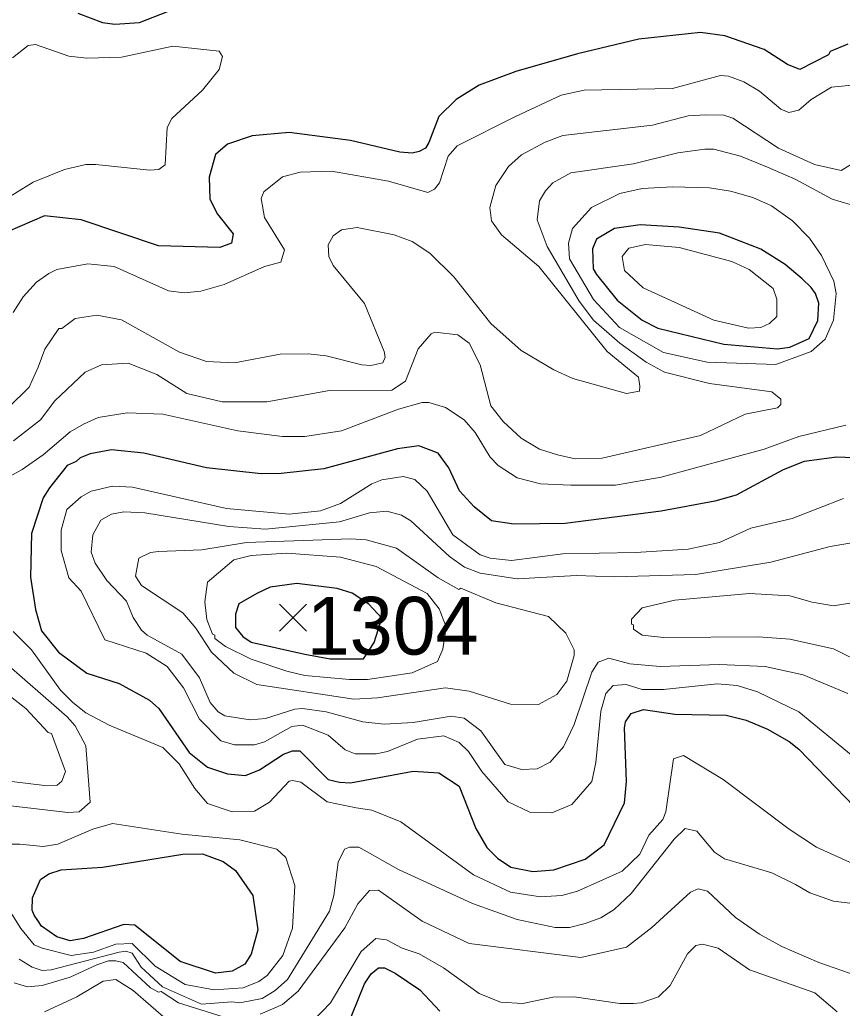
# Model space of a CAD drawing. Extents: x 423 to 448.8, y 7456.3 to 7484.
# Drawn here: x 432.388 to 433.527, y 7475.791 to 7477.16 of the extents above; entities that cross this region are included whole.
import ezdxf
from ezdxf.enums import TextEntityAlignment as Align

# ---------------------------------------------------------------- set-up
doc = ezdxf.new("R2010")
doc.units = 0
doc.header["$LTSCALE"] = 0.032
for name, color, linetype, lineweight in [('1', 7, 'Continuous', 25), ('2', 7, 'Continuous', 13), ('21', 7, 'Continuous', 25)]:
    doc.layers.add(name, color=color, linetype=linetype, lineweight=lineweight)
doc.layers.add('61', color=7, linetype='Continuous')

msp = doc.modelspace()

# ---------------------------------------------------------------- linework, layer by layer
at = {"layer": '1'}
for points in [[(432.4688, 7477.1694), (432.5028, 7477.1562), (432.5198, 7477.1539), (432.5538, 7477.1562), (432.6343, 7477.1879)], [(433.5346, 7477.1261), (433.5098, 7477.116), (433.5075, 7477.1114), (433.4681, 7477.0912), (433.451, 7477.0982), (433.4186, 7477.1191), (433.3644, 7477.1377), (433.3304, 7477.1423), (433.2453, 7477.133), (433.1602, 7477.1129), (433.0751, 7477.0882), (433.0241, 7477.0696), (432.9924, 7477.0495), (432.9684, 7477.0263), (432.9545, 7476.9899), (432.9498, 7476.9822), (432.9413, 7476.9775), (432.9313, 7476.9752), (432.9143, 7476.9768), (432.8462, 7476.993), (432.7611, 7477.0039), (432.7101, 7476.9992), (432.676, 7476.9876), (432.659, 7476.9737), (432.6505, 7476.942), (432.6512, 7476.9118), (432.6621, 7476.8909), (432.6837, 7476.8638), (432.6814, 7476.8507), (432.6652, 7476.8445), (432.5801, 7476.8468), (432.4734, 7476.8832), (432.4223, 7476.8886), (432.3713, 7476.8662)], [(433.5771, 7476.5522), (433.5191, 7476.5544), (433.4742, 7476.5483), (433.4449, 7476.5367), (433.3799, 7476.5019), (433.3505, 7476.4934), (433.2762, 7476.4794), (433.1432, 7476.4624), (433.072, 7476.4616), (433.0411, 7476.4663), (433.0171, 7476.4856), (432.997, 7476.508), (432.9823, 7476.5398), (432.9676, 7476.5599), (432.9406, 7476.5699), (432.9112, 7476.5661), (432.8091, 7476.5382), (432.7503, 7476.532), (432.7224, 7476.5313), (432.6466, 7476.5398)], [(432.6466, 7476.5398), (432.56, 7476.5599), (432.5152, 7476.5645), (432.4858, 7476.5591), (432.4718, 7476.5537), (432.4664, 7476.5483), (432.454, 7476.5429), (432.4293, 7476.5119), (432.4208, 7476.498), (432.4045, 7476.4485), (432.403, 7476.3882), (432.41, 7476.3433), (432.4184, 7476.3139), (432.4417, 7476.2845), (432.4811, 7476.2551), (432.526, 7476.2412), (432.5677, 7476.218), (432.5809, 7476.2064), (432.6227, 7476.1453), (432.6482, 7476.1252), (432.676, 7476.1159), (432.7007, 7476.1136), (432.7201, 7476.1213), (432.7534, 7476.143), (432.7658, 7476.1476), (432.7758, 7476.1476), (432.8152, 7476.1082), (432.8307, 7476.1043), (432.8462, 7476.1035), (432.9328, 7476.1198), (432.9684, 7476.1174), (432.9963, 7476.0989), (433.0194, 7476.0401), (433.0349, 7476.0138), (433.0496, 7475.9991), (433.0681, 7475.9868), (433.0983, 7475.9806), (433.1277, 7475.9829), (433.1711, 7475.9976), (433.1973, 7476.0177), (433.2252, 7476.0757), (433.2283, 7476.1051), (433.2252, 7476.1794), (433.2267, 7476.1878), (433.2345, 7476.1994), (433.2515, 7476.2048), (433.2948, 7476.1987), (433.366, 7476.1971), (433.3938, 7476.1902), (433.4232, 7476.1778), (433.4533, 7476.1608), (433.4665, 7476.1499), (433.5562, 7476.0571)], [(432.8392, 7475.7601), (432.8655, 7475.8251), (432.8748, 7475.839), (432.8848, 7475.8475), (432.8933, 7475.8475), (432.9081, 7475.8398), (432.9421, 7475.8166), (432.9699, 7475.7872)]]:
    msp.add_lwpolyline(points, dxfattribs=at)
for points in [[(433.4837, 7476.7893), (433.4711, 7476.8012), (433.4479, 7476.8213), (433.4139, 7476.8422), (433.3567, 7476.8646), (433.301, 7476.8731), (433.2469, 7476.8762), (433.2113, 7476.8708), (433.1865, 7476.8561), (433.1811, 7476.843), (433.1818, 7476.8151), (433.1865, 7476.8074), (433.2151, 7476.7718), (433.2499, 7476.7439), (433.2716, 7476.7331), (433.3629, 7476.7107), (433.4371, 7476.7045), (433.4541, 7476.7068), (433.4808, 7476.7188), (433.4928, 7476.7436), (433.4943, 7476.7676), (433.4897, 7476.7811)], [(432.7828, 7476.2814), (432.8181, 7476.2753), (432.8639, 7476.2753), (432.879, 7476.2979), (432.8893, 7476.3315), (432.8715, 7476.3507), (432.8486, 7476.3661), (432.8276, 7476.3727), (432.7719, 7476.3796), (432.7348, 7476.3743), (432.7163, 7476.3657), (432.6915, 7476.3511), (432.6869, 7476.3371), (432.6869, 7476.3186), (432.6969, 7476.3062), (432.7085, 7476.2984)], [(432.4455, 7475.9828), (432.5028, 7475.9868), (432.6142, 7476.0045), (432.6412, 7476.0053), (432.6699, 7475.9945), (432.6868, 7475.9821), (432.7108, 7475.9473), (432.7178, 7475.9001), (432.7085, 7475.8661), (432.7, 7475.8522), (432.6822, 7475.8429), (432.659, 7475.8398), (432.6103, 7475.856), (432.5476, 7475.9063), (432.5322, 7475.9071), (432.4765, 7475.8877), (432.4579, 7475.8846), (432.4394, 7475.8901), (432.4184, 7475.9048), (432.4133, 7475.9127), (432.4084, 7475.9202), (432.4053, 7475.9272), (432.4061, 7475.9442), (432.4169, 7475.9697), (432.4285, 7475.9775)]]:
    msp.add_lwpolyline(points, close=True, dxfattribs=at)
at = {"layer": '2'}
for points in [[(432.3782, 7477.1075), (432.3999, 7477.1245), (432.41, 7477.126), (432.4564, 7477.1098), (432.4811, 7477.1067), (432.5291, 7477.1082), (432.6002, 7477.1237), (432.6644, 7477.1167), (432.6691, 7477.109), (432.6644, 7477.0912), (432.6412, 7477.0626), (432.5986, 7477.0232), (432.5925, 7477.0108), (432.5894, 7476.959), (432.5809, 7476.9528), (432.5678, 7476.952), (432.4935, 7476.9598), (432.4796, 7476.9598), (432.4502, 7476.9528), (432.4069, 7476.935), (432.3048, 7476.8723)], [(432.379, 7476.7548), (432.3929, 7476.7765), (432.4115, 7476.7965), (432.4285, 7476.8089), (432.4394, 7476.8143), (432.4827, 7476.8221), (432.519, 7476.8182), (432.5941, 7476.7849), (432.6157, 7476.7819), (432.6389, 7476.7842), (432.6714, 7476.7935), (432.7271, 7476.8182), (432.7495, 7476.8244), (432.7549, 7476.8414), (432.727, 7476.8863), (432.7224, 7476.9126), (432.7263, 7476.9218), (432.7518, 7476.9427), (432.7766, 7476.9489), (432.8199, 7476.9505), (432.8988, 7476.9366), (432.9529, 7476.9211), (432.9622, 7476.9257), (432.9692, 7476.9342), (432.9815, 7476.9714), (432.9939, 7476.9853), (433.0743, 7477.0263), (433.1378, 7477.0557), (433.1695, 7477.0626), (433.2917, 7477.0649), (433.3582, 7477.0828), (433.3691, 7477.082), (433.3907, 7477.0742), (433.4124, 7477.0611), (433.4418, 7477.0363), (433.4526, 7477.0317), (433.4665, 7477.0348), (433.4835, 7477.0495), (433.5121, 7477.0665), (433.5547, 7477.0711)], [(433.3134, 7477.0271), (433.2639, 7477.0139), (433.1401, 7477), (433.1154, 7476.9907), (433.0829, 7476.9729), (433.065, 7476.9567), (433.0473, 7476.9304), (433.0388, 7476.9002), (433.0411, 7476.8817), (433.055, 7476.8623), (433.1068, 7476.8182), (433.2012, 7476.7006), (433.2445, 7476.6651), (433.2468, 7476.6527), (433.2461, 7476.6457), (433.2283, 7476.6426), (433.154, 7476.6635), (433.1277, 7476.6751), (433.0821, 7476.7022), (433.0403, 7476.7393), (432.9893, 7476.8043), (432.956, 7476.8368), (432.9313, 7476.853), (432.9065, 7476.8623), (432.8555, 7476.8723), (432.8338, 7476.8692), (432.8222, 7476.8608), (432.8153, 7476.8484), (432.816, 7476.8322), (432.8222, 7476.8198), (432.8655, 7476.7672), (432.8926, 7476.7007), (432.8941, 7476.6929), (432.891, 7476.6852), (432.874, 7476.6813), (432.8617, 7476.6821), (432.8122, 7476.6945), (432.7874, 7476.6976), (432.7487, 7476.6968), (432.6853, 7476.6852), (432.6466, 7476.6867), (432.6095, 7476.6999), (432.529, 7476.7447), (432.495, 7476.7509), (432.4649, 7476.7463), (432.4463, 7476.7324), (432.4424, 7476.7324), (432.4231, 7476.7038), (432.4138, 7476.679), (432.4014, 7476.6512), (432.3728, 7476.6233)], [(433.5384, 7476.959), (433.5253, 7476.9512), (433.4882, 7476.9597), (433.4387, 7476.9822), (433.3752, 7477.024), (433.3629, 7477.0278), (433.3381, 7477.0286), (433.3134, 7477.0271)], [(433.5377, 7476.9041), (433.5129, 7476.9118), (433.4626, 7476.9389), (433.4232, 7476.9559), (433.3861, 7476.9714), (433.3489, 7476.9807), (433.3366, 7476.9807), (433.2994, 7476.976), (433.2376, 7476.9605), (433.1509, 7476.9482), (433.1262, 7476.9342), (433.1161, 7476.9234), (433.1076, 7476.9095), (433.1045, 7476.8832), (433.1184, 7476.8461), (433.1625, 7476.7703), (433.1826, 7476.744), (433.219, 7476.7123), (433.2553, 7476.686), (433.2809, 7476.672), (433.3428, 7476.6565), (433.4294, 7476.6449)], [(433.4294, 7476.6449), (433.4418, 7476.6349), (433.4418, 7476.6272), (433.4371, 7476.6225), (433.3923, 7476.614), (433.3304, 7476.5846), (433.1943, 7476.5529), (433.1571, 7476.5522), (433.1324, 7476.5575), (433.1076, 7476.5653), (433.0821, 7476.5807), (433.0573, 7476.604), (433.0403, 7476.6256), (433.0256, 7476.6821), (433.0102, 7476.7122), (432.9947, 7476.7239), (432.963, 7476.7277), (432.9576, 7476.7254), (432.9398, 7476.7045), (432.922, 7476.6596), (432.9034, 7476.6473), (432.8168, 7476.6465), (432.7302, 7476.6311), (432.6683, 7476.6311), (432.6195, 7476.6426), (432.5778, 7476.6689), (432.5384, 7476.6844), (432.5012, 7476.6821), (432.4788, 7476.672), (432.437, 7476.6326), (432.4169, 7476.6063), (432.3798, 7476.5769)], [(433.5315, 7476.5985), (433.4665, 7476.5831), (433.4186, 7476.5653), (433.2762, 7476.5266), (433.2128, 7476.5158), (433.1509, 7476.5158), (433.1092, 7476.5173), (433.0767, 7476.5258), (433.0504, 7476.5428), (433.0395, 7476.5545), (433.0187, 7476.5885), (433.0032, 7476.6063), (432.9776, 7476.6233), (432.9545, 7476.6303), (432.9452, 7476.6303), (432.9127, 7476.621), (432.8338, 7476.5908), (432.7828, 7476.5831), (432.7518, 7476.5831), (432.69, 7476.5908), (432.5863, 7476.614), (432.5368, 7476.6156), (432.4966, 7476.6094), (432.4764, 7476.6001), (432.4579, 7476.5893), (432.4208, 7476.5575), (432.3914, 7476.5375), (432.3372, 7476.5073)], [(433.5284, 7476.4972), (433.4572, 7476.4694), (433.4, 7476.4562), (433.3567, 7476.4361), (433.3134, 7476.4269), (433.2407, 7476.4222), (433.1401, 7476.4207), (433.069, 7476.4114), (433.0396, 7476.4145), (433.0256, 7476.4191), (432.9877, 7476.4469), (432.9521, 7476.5073), (432.9351, 7476.5235), (432.9189, 7476.5274), (432.8895, 7476.5228), (432.8756, 7476.5173), (432.8323, 7476.4902), (432.8044, 7476.4802), (432.7611, 7476.4756), (432.6745, 7476.4833), (432.5445, 7476.5127), (432.5167, 7476.5142), (432.4873, 7476.5073), (432.4734, 7476.4995), (432.4533, 7476.4818), (432.4455, 7476.4532), (432.4455, 7476.4253), (432.4564, 7476.3874), (432.4734, 7476.3688), (432.5059, 7476.3015), (432.5631, 7476.283), (432.5925, 7476.2644), (432.6149, 7476.235), (432.6373, 7476.1917), (432.6668, 7476.1615), (432.6853, 7476.1561), (432.7132, 7476.1561), (432.7271, 7476.16), (432.765, 7476.1816), (432.7797, 7476.1832), (432.8152, 7476.1693), (432.8385, 7476.1492), (432.8524, 7476.1437), (432.8818, 7476.1437), (432.8972, 7476.1468), (432.939, 7476.1639), (432.9754, 7476.1685), (432.9963, 7476.1592), (433.0094, 7476.1468), (433.0279, 7476.119), (433.0643, 7476.0773), (433.0953, 7476.0625), (433.1246, 7476.0618), (433.1524, 7476.0734), (433.1803, 7476.1051), (433.1857, 7476.1314), (433.1927, 7476.2026), (433.1996, 7476.2273), (433.2097, 7476.2381), (433.2275, 7476.2397), (433.2499, 7476.2327), (433.2793, 7476.2327), (433.3536, 7476.2404), (433.3814, 7476.2381), (433.4093, 7476.2296), (433.4665, 7476.2018), (433.5547, 7476.1291)], [(433.5887, 7476.4439), (433.5098, 7476.4307), (433.4278, 7476.409), (433.3242, 7476.392), (433.2113, 7476.3889), (433.1587, 7476.3905), (433.0767, 7476.3858), (433.0256, 7476.3936), (433.004, 7476.4021), (432.9831, 7476.4168), (432.9297, 7476.4663), (432.9166, 7476.474), (432.8964, 7476.4794), (432.8725, 7476.4771), (432.8307, 7476.4647), (432.7286, 7476.4547), (432.6776, 7476.4585), (432.5616, 7476.4771), (432.5322, 7476.4787), (432.5152, 7476.4756), (432.5004, 7476.467), (432.4896, 7476.447), (432.4873, 7476.423), (432.4927, 7476.4075), (432.5089, 7476.3836), (432.536, 7476.3549), (432.5453, 7476.3325), (432.5569, 7476.3147), (432.5646, 7476.3077), (432.6126, 7476.2814), (432.6373, 7476.249), (432.652, 7476.2149), (432.6629, 7476.2018), (432.6722, 7476.1964), (432.707, 7476.1909), (432.7286, 7476.1925), (432.7689, 7476.2056), (432.7797, 7476.2064), (432.8122, 7476.2018), (432.8632, 7476.1878), (432.8926, 7476.1848), (432.9328, 7476.1871), (432.9854, 7476.1956), (433.0032, 7476.1932), (433.0264, 7476.1755), (433.0597, 7476.129), (433.0829, 7476.1221), (433.1045, 7476.1229), (433.1223, 7476.1322), (433.1409, 7476.1531), (433.1556, 7476.184), (433.1803, 7476.2567), (433.1888, 7476.2706), (433.2035, 7476.276), (433.2329, 7476.2683), (433.2747, 7476.2644), (433.3567, 7476.2675), (433.4201, 7476.2644), (433.4727, 7476.2528), (433.5346, 7476.2273)], [(433.5593, 7476.2667), (433.5145, 7476.2892), (433.4541, 7476.3023), (433.4108, 7476.3054), (433.2793, 7476.3046), (433.2499, 7476.3077), (433.2376, 7476.3162), (433.2376, 7476.3224), (433.2352, 7476.3232), (433.2352, 7476.3302), (433.2499, 7476.3456), (433.2948, 7476.3564), (433.3984, 7476.3657), (433.4541, 7476.3626), (433.4851, 7476.3534), (433.5145, 7476.3487), (433.5454, 7476.3534)], [(432.379, 7476.3131), (432.4045, 7476.2876), (432.4448, 7476.2319), (432.4618, 7476.2149), (432.4796, 7476.2002), (432.5121, 7476.1832), (432.5863, 7476.1523), (432.6087, 7476.1299), (432.6304, 7476.0958), (432.6482, 7476.0749), (432.6822, 7476.0633), (432.7132, 7476.0641), (432.734, 7476.0765), (432.7611, 7476.1059), (432.7658, 7476.1066), (432.7773, 7476.1043), (432.8137, 7476.0772), (432.8539, 7476.0687), (432.8756, 7476.0656), (432.9158, 7476.0494), (433.0163, 7475.9759), (433.0674, 7475.952), (433.1092, 7475.9457), (433.1386, 7475.9473), (433.1602, 7475.9535), (433.2221, 7475.9813), (433.2468, 7476.0046), (433.2592, 7476.0308), (433.2785, 7476.0525), (433.2824, 7476.0633), (433.2932, 7476.1368), (433.3072, 7476.1414), (433.3621, 7476.1082), (433.4533, 7476.0393), (433.4913, 7476.0146), (433.5949, 7475.9674)], [(432.362, 7476.2753), (432.454, 7476.1948), (432.4649, 7476.1825), (432.4796, 7476.1546), (432.4858, 7476.0765), (432.4703, 7476.0633), (432.4548, 7476.0625), (432.3558, 7476.0741)], [(432.348, 7476.2443), (432.3968, 7476.2064), (432.4277, 7476.1732), (432.4324, 7476.1716), (432.4517, 7476.119), (432.4463, 7476.1059), (432.4401, 7476.1004), (432.4223, 7476.0997), (432.3202, 7476.1121)], [(432.3651, 7476.0185), (432.3883, 7476.0184), (432.4208, 7476.0154), (432.4409, 7476.0185), (432.4896, 7476.0393), (432.5167, 7476.0471), (432.6126, 7476.0324), (432.6931, 7476.0247), (432.7441, 7476.0115), (432.7565, 7475.9999), (432.7688, 7475.9612), (432.7658, 7475.9024), (432.7526, 7475.8645), (432.7309, 7475.8367), (432.7194, 7475.8282), (432.6977, 7475.8197), (432.6575, 7475.8166), (432.6173, 7475.8243), (432.5755, 7475.8498), (432.5438, 7475.8808), (432.5213, 7475.88), (432.4904, 7475.8692), (432.4595, 7475.8645), (432.4192, 7475.8746), (432.4084, 7475.8792), (432.3898, 7475.9017), (432.3612, 7475.9473)], [(432.3875, 7475.8591), (432.4053, 7475.8483), (432.4192, 7475.8437), (432.4316, 7475.8444), (432.5258, 7475.869), (432.5352, 7475.8705), (432.5439, 7475.8678), (432.5564, 7475.8484), (432.5858, 7475.821), (432.6399, 7475.797), (432.6819, 7475.8), (432.6931, 7475.7988), (432.724, 7475.805), (432.7418, 7475.8158), (432.7588, 7475.8313), (432.8168, 7475.9257), (432.823, 7475.9473), (432.8292, 7475.9937), (432.8377, 7476.0115), (432.8446, 7476.0146), (432.8578, 7476.0146), (432.9127, 7475.9836), (433.0148, 7475.9365), (433.0767, 7475.914), (433.1293, 7475.9032), (433.1493, 7475.9032), (433.1711, 7475.9086), (433.1927, 7475.9163), (433.2112, 7475.9279), (433.2344, 7475.9504), (433.294, 7476.0254), (433.3095, 7476.0401), (433.3257, 7476.0363), (433.3497, 7476.0076), (433.3636, 7475.9984), (433.4294, 7475.979), (433.4619, 7475.9628), (433.482, 7475.9512), (433.5145, 7475.9396), (433.5856, 7475.931)], [(432.7209, 7475.7833), (432.7518, 7475.7965), (432.7735, 7475.815), (432.8384, 7475.9025), (432.8562, 7475.9357), (432.8725, 7475.9542), (432.8849, 7475.955), (432.9452, 7475.9117), (433.0102, 7475.8808), (433.1649, 7475.8614), (433.2283, 7475.8761), (433.2631, 7475.9032), (433.3165, 7475.952), (433.3273, 7475.9566), (433.3404, 7475.9535), (433.3791, 7475.9171), (433.4123, 7475.8939), (433.4433, 7475.8769), (433.4944, 7475.8545), (433.5686, 7475.8289), (433.5926, 7475.8166), (433.6189, 7475.7849)], [(433.5199, 7475.7864), (433.4889, 7475.8127), (433.3984, 7475.8444), (433.3551, 7475.8746), (433.3335, 7475.88), (433.3242, 7475.8784), (433.3126, 7475.8668), (433.2886, 7475.8228), (433.2724, 7475.8073), (433.2484, 7475.7988), (433.2376, 7475.798), (433.219, 7475.798), (433.1556, 7475.8073), (433.1262, 7475.8065), (433.0844, 7475.798), (433.0535, 7475.7996), (433.0241, 7475.8119), (432.9746, 7475.8475), (432.9413, 7475.8669), (432.9174, 7475.8746), (432.8957, 7475.8862), (432.881, 7475.8877), (432.8609, 7475.8699), (432.8183, 7475.7988), (432.7944, 7475.774)], [(432.4579, 7475.8344), (432.495, 7475.8514), (432.5113, 7475.8568), (432.5213, 7475.8568), (432.5314, 7475.8545), (432.5693, 7475.8197), (432.5801, 7475.8135), (432.5838, 7475.8147), (432.608, 7475.7988), (432.6699, 7475.7794)], [(432.3806, 7475.8267), (432.3991, 7475.8212), (432.4192, 7475.8228), (432.4579, 7475.8344)], [(432.594, 7475.7733), (432.5453, 7475.8158), (432.5213, 7475.8313), (432.5035, 7475.8289), (432.4672, 7475.8073), (432.4223, 7475.7864)]]:
    msp.add_lwpolyline(points, dxfattribs=at)
for points in [[(433.403, 7476.9141), (433.4286, 7476.9025), (433.458, 7476.8816), (433.4812, 7476.8577), (433.4982, 7476.8337), (433.5152, 7476.7981), (433.5183, 7476.7811), (433.5145, 7476.744), (433.5029, 7476.7177), (433.4835, 7476.7006), (433.4347, 7476.6827), (433.3397, 7476.686), (433.2793, 7476.6991), (433.2182, 7476.7339), (433.1826, 7476.7726), (433.1494, 7476.8291), (433.1478, 7476.8507), (433.1532, 7476.8708), (433.1795, 7476.9002), (433.219, 7476.9195), (433.2499, 7476.9265), (433.2917, 7476.9288), (433.3428, 7476.9273), (433.3722, 7476.9226)], [(433.4363, 7476.7494), (433.4363, 7476.7734), (433.4309, 7476.788), (433.3977, 7476.8143), (433.3737, 7476.8252), (433.301, 7476.8445), (433.2546, 7476.8491), (433.2314, 7476.8437), (433.2221, 7476.8322), (433.2252, 7476.8128), (433.2514, 7476.7888), (433.3489, 7476.744), (433.3969, 7476.7331), (433.4139, 7476.7339), (433.4262, 7476.7393)], [(433.0674, 7476.2125), (433.1061, 7476.2118), (433.1316, 7476.2257), (433.1455, 7476.2443), (433.1556, 7476.2799), (433.1556, 7476.2876), (433.144, 7476.3108), (433.12, 7476.334), (433.0473, 7476.3526), (432.9989, 7476.3731), (432.9962, 7476.3711), (432.9676, 7476.3874), (432.9096, 7476.4284), (432.8679, 7476.44), (432.8462, 7476.4415), (432.7023, 7476.4361), (432.6405, 7476.4261), (432.5801, 7476.4238), (432.5693, 7476.4222), (432.553, 7476.4144), (432.5484, 7476.3897), (432.5569, 7476.3766), (432.6142, 7476.3387), (432.6319, 7476.3178), (432.6536, 7476.2845), (432.6845, 7476.2551), (432.7163, 7476.2396), (432.8508, 7476.2195), (432.8833, 7476.2211), (432.9777, 7476.235), (433.0102, 7476.2304)], [(432.9688, 7476.3444), (432.9523, 7476.3654), (432.8818, 7476.4029), (432.8323, 7476.416), (432.758, 7476.4214), (432.7085, 7476.4183), (432.6845, 7476.4121), (432.6482, 7476.3812), (432.6443, 7476.3542), (432.6474, 7476.3294), (432.6551, 7476.3093), (432.6582, 7476.3077), (432.6582, 7476.3031), (432.6729, 7476.2922), (432.7085, 7476.2745), (432.758, 7476.2582), (432.7828, 7476.252), (432.8447, 7476.2466), (432.8694, 7476.2466), (432.9313, 7476.2559), (432.9666, 7476.2714), (432.9741, 7476.2886), (432.9786, 7476.3193)]]:
    msp.add_lwpolyline(points, close=True, dxfattribs=at)
at = {"layer": '21'}
for p, q in [((432.7479, 7476.351), (432.7854, 7476.3135)), ((432.7854, 7476.351), (432.7479, 7476.3135))]:
    msp.add_line(p, q, dxfattribs=at)

# ---------------------------------------------------------------- texts
at = {"layer": '61'}
msp.add_text('1304', height=0.08, dxfattribs=at).set_placement((432.9045, 7476.281), align=Align.CENTER)

doc.saveas('drawing.dxf')
